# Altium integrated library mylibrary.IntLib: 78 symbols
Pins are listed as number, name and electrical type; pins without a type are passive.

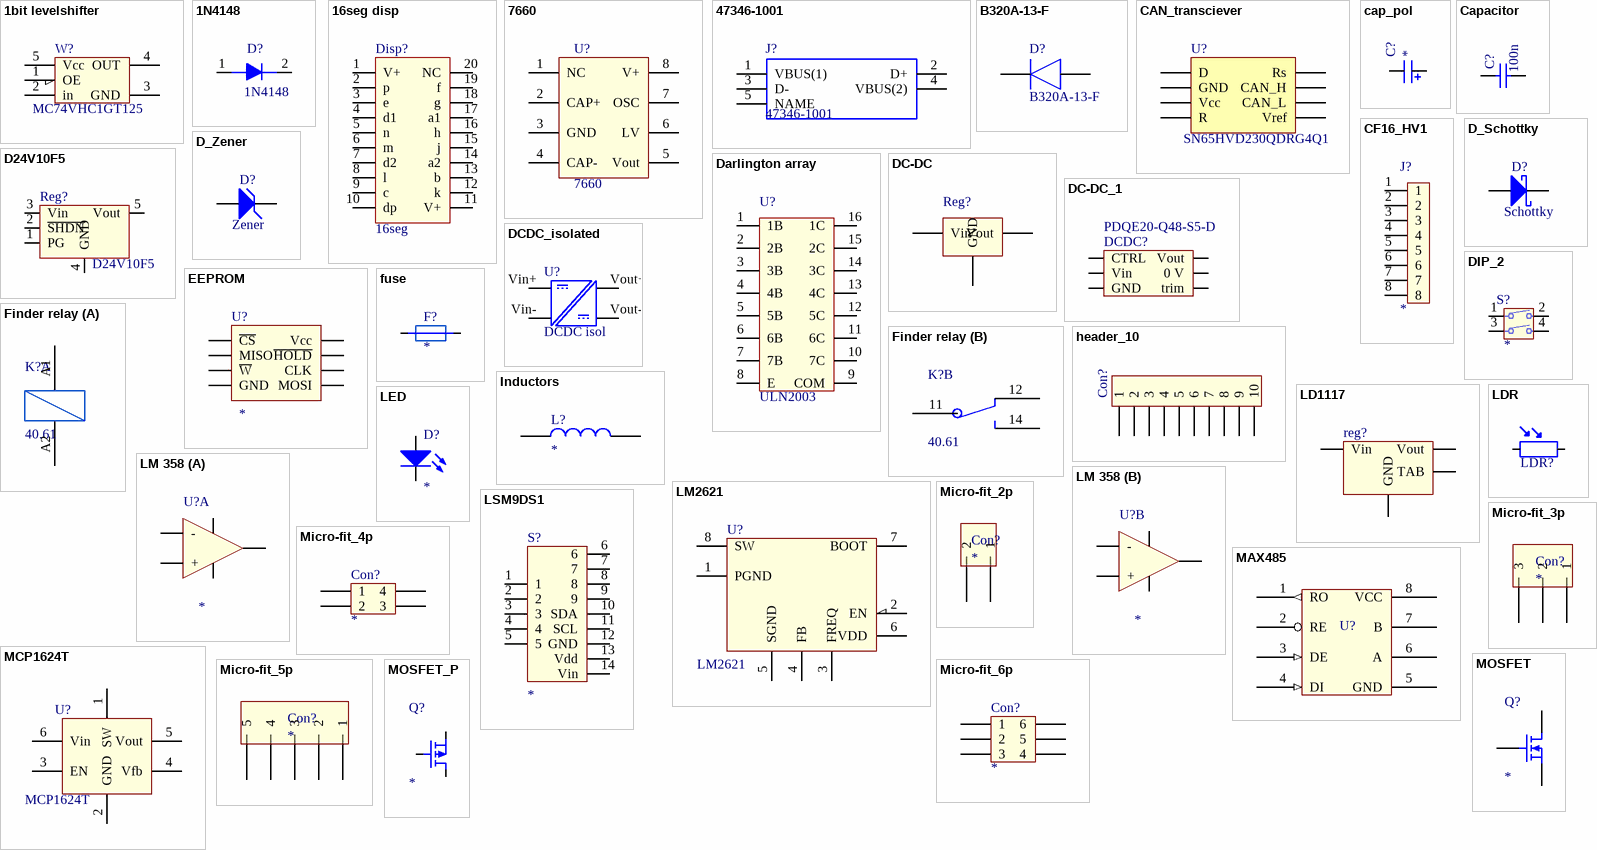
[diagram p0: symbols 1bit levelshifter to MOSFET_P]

## 1bit levelshifter
designator W?, comment MC74VHC1GT125
footprint SOT-353
pins: 1 OE, 2 in, 3 GND, 4 OUT, 5 Vcc

## 1N4148
designator D?
footprint 1N4148 (QuadroMELF (SOD-80))
pins: 1, 2

## 16seg disp
designator Disp?, comment 16seg
footprint PSA23-11SRWA (16 seg display)
pins: 1 V+, 2 p, 3 e, 4 d1, 5 n, 6 m, 7 d2, 8 l, 9 c, 10 dp, 11 V+, 12 k, 13 b, 14 a2, 15 j, 16 h, 17 a1, 18 g, 19 f, 20 NC

## 7660
designator U?
footprint SOIC127P600X170-8N (SOIC, 8-Leads, Body 4,90x3,90mm, Pitch 1,27mm, IPC Medium Density)
pins: 1 NC, 2 CAP+, 3 GND, 4 CAP-, 5 Vout, 6 LV, 7 OSC, 8 V+

## 47346-1001
designator J?
MOLEX - 47346-1001 - MULTIPOLE CONNECTOR
footprint 47346-0001
pins: 1 VBUS(1), 2 D+, 3 D-, 4 VBUS(2), 5 NAME

## B320A-13-F
designator D?
Diode Schottky 20V 3A 2Pin SMA Diodes Inc B320A-13-F, SMT Schottky Diode, 20V 3A, 2-Pin DO-214AC; Manufacturer_Name: Diodes Inc.; Allied_Number: 70437560; Geometry.Height: 2.2mm
footprint DIOM5226X220N
pins: 1 K, 2 A

## CAN_transciever
designator U?, comment SN65HVD230QDRG4Q1
SN65HVD230QDRG4Q1 SO-8
footprint SO-8 (SOIC, 8-Leads, Body 4,90x3,90mm, Pitch 1,27mm, IPC Medium Density)
pins: 1 D, 2 GND, 3 Vcc, 4 R, 5 Vref, 6 CAN_L, 7 CAN_H, 8 Rs

## cap_pol
designator C?
footprint CAP_5x5.5 (Aluminum Electrolytic Capacitor, Body 5,30x5,30x5,80mm, IPC Low Density)
footprint 1206_tantal (3216-18 AVX)
footprint elko_D5 (5mm diameter THT elko)
footprint 2917_pol (Vishay tantalum)
footprint UHE1A472MHD (12.5x35.5 ALU ELKO)
footprint 8x20 mm ELKO
footprint CAP_6.3x7.7 (6,3x7,7)
pins: 1, 2

## Capacitor
designator C?, comment 100n
footprint 0805_cap
footprint CAP0603
footprint cap 2.54 THT (ceramic THT capacitor)
footprint 1206_cap
pins: 1, 2

## CF16_HV1
designator J?
footprint CF16-HV1
pins: 1, 2, 3, 4, 5, 6, 7, 8

## D24V10F5
designator Reg?
footprint D24V10F5
pins: 1 PG, 2 ~{SHDN}, 3 Vin, 4 GND, 5 Vout

## D_Schottky
designator D?, comment Schottky
footprint DO-214AC (Molded Diode, 2-Leads, Body 4,31x2,49mm)
pins: 1, 2

## D_Zener
designator D?, comment Zener
footprint SOD-123 (SODFL, 2-Leads, Body 1,60x3,75mm)
pins: 1, 2

## Darlington array
designator U?, comment ULN2003
footprint SOP16
pins: 1 1B, 2 2B, 3 3B, 4 4B, 5 5B, 6 6B, 7 7B, 8 E, 9 COM, 10 7C, 11 6C, 12 5C, 13 4C, 14 3C, 15 2C, 16 1C

## DC-DC
designator Reg?  (value not drawn)
Adjustable voltage supply
footprint SIP3
footprint SIP3 - vert
footprint VXO7805-500
footprint VXO7805-1000
footprint VXO7805-500 - flat (flattened edition)
pins: 1 Vin, 2 GND, 3 Vout

## DC-DC_1
designator DCDC?, comment PDQE20-Q48-S5-D
footprint PDQE20-Q48-S5-D (CUI DC-DC 5V@4A)
pins: 1 CTRL, 2 GND, 3 Vin, 4 Vout, 5 trim, 6 0 V

## DCDC_isolated
designator U?, comment DCDC isol
footprint RI3
footprint SIP7-4 (4 pin SIP7 package)
pins: Vin+, Vin-, Vout+, Vout-

## DIP_2
designator S?
footprint 1-2319848-2
pins: 1, 2, 3, 4

## EEPROM
designator U?
M95512-DFMN6TP
footprint SO-8 (SOIC, 8-Leads, Body 4,90x3,90mm, Pitch 1,27mm, IPC Medium Density)
pins: 1 ~{CS}, 2 MISO, 3 ~{W}, 4 GND, 5 MOSI, 6 CLK, 7 ~{HOLD}, 8 Vcc

## Finder relay
designator K?, comment 40.61
footprint Finder 40.61 (40.61.7.012.2020 SPDT 16A)
part A pins: A1, A2
part B pins: 11, 12, 14

## fuse
designator F?
footprint Littelfuse_01530008 (Fuse holder w fuse)
footprint 3557-2 (Keystone fuse holder w fuse)
footprint 3557 (Keystone fuse holder w fuse)
footprint 1206_fuse (Bell fuse)
pins: 1, 2

## header_10
designator Con?, comment Header_10  (value not drawn)
footprint BM10B-SRSS-TB (1mm pitch JST-SH)
pins: 1, 2, 3, 4, 5, 6, 7, 8, 9, 10

## Inductors
designator L?
footprint 1812 (1812 size inductor)
footprint HC1-100-R (Precision Wire Wound Inductor, 2-Leads, Body 13,00x13,00mm, IPC Medium Density)
pins: 1, 2

## LD1117
designator reg?  (value not drawn)
footprint SOT230P700X180-4N (SOT223, 4-Leads, Body 6,50x7,00mm (avg), Pitch 2,30mm, IPC Medium Density)
footprint SOT223
pins: 1 GND, 2 Vout, 3 Vin, 4 TAB

## LDR
designator LDR?  (value not drawn)
footprint LDR (pitch 3.7mm)
pins: 1, 2

## LED
designator D?
footprint LED_5mm (std 5mm LED)
footprint EVL-BHC-AN1P2 (0805_Blue)
footprint EVL-GHC-XS1T2M (0805_Green)
footprint EVL-R6C-AQ1R2B (0805_Red)
footprint EVL-Y2C-CP2Q2B (0805_Yellow)
pins: 1, 2

## LM2621
designator U?
footprint VSSOP_8
pins: 1 PGND (power), 2 EN, 3 FREQ, 4 FB, 5 SGND (power), 6 VDD (power), 7 BOOT (power), 8 SW (power)

## LM 358
designator U?
footprint SO-8 (SOIC, 8-Leads, Body 4,90x3,90mm, Pitch 1,27mm, IPC Medium Density)
part A pins: 1 out, 2 -, 3 +, 4 GND, 8 Vcc
part B pins: 4 GND, 5 +, 6 -, 7 out, 8 Vcc

## LSM9DS1
designator S?
footprint DS1
pins: 1, 2, 3, 4, 5, 6, 7, 8, 9, 10 SDA, 11 SCL, 12 GND, 13 Vdd, 14 Vin

## MAX485
designator U?  (value not drawn)
footprint DIP8
footprint SOIC127P600X170-8N (SOIC, 8-Leads, Body 4,90x3,90mm, Pitch 1,27mm, IPC Medium Density)
pins: 1 RO (out), 2 RE, 3 DE (in), 4 DI (in), 5 GND (power), 6 A, 7 B, 8 VCC (power)

## MCP1624T
designator U?
footprint SOT23 (SOT23, 6-Leads, Body 2,90x3,10mm, Pitch 0,95mm, IPC Medium Density)
pins: 1 SW, 2 GND, 3 EN, 4 Vfb, 5 Vout, 6 Vin

## Micro-fit_2p
designator Con?
footprint Micro-fit_2P (horizontal)
pins: 1, 2

## Micro-fit_3p
designator Con?
footprint Micro-fit_3P (horizontal)
footprint Micro-fit_3P_v (vertical)
pins: 1, 2, 3

## Micro-fit_4p
designator Con?
footprint Micro-fit_4P (THT, double row, vertical)
pins: 1, 2, 3, 4

## Micro-fit_5p
designator Con?
footprint Micro-fit_5P (horizontal)
pins: 1, 2, 3, 4, 5

## Micro-fit_6p
designator Con?
footprint Micro-fit_6P (THT, double row, vertical)
pins: 1, 2, 3, 4, 5, 6

## MOSFET
designator Q?
footprint SOT323 (SOT23, 3-Leads, Body 1,90x2,10mm, Pitch 0,65mm, IPC Medium Density)
footprint SOT23-3 (DMN6140LQ-7)
footprint TO-220-3
pins: D, G, S

## MOSFET_P
designator Q?
footprint SOT323 (SOT23, 3-Leads, Body 1,90x2,10mm, Pitch 0,65mm, IPC Medium Density)
footprint SOT23-3 (DMN6140LQ-7)
footprint TO-220-3
pins: D, G, S

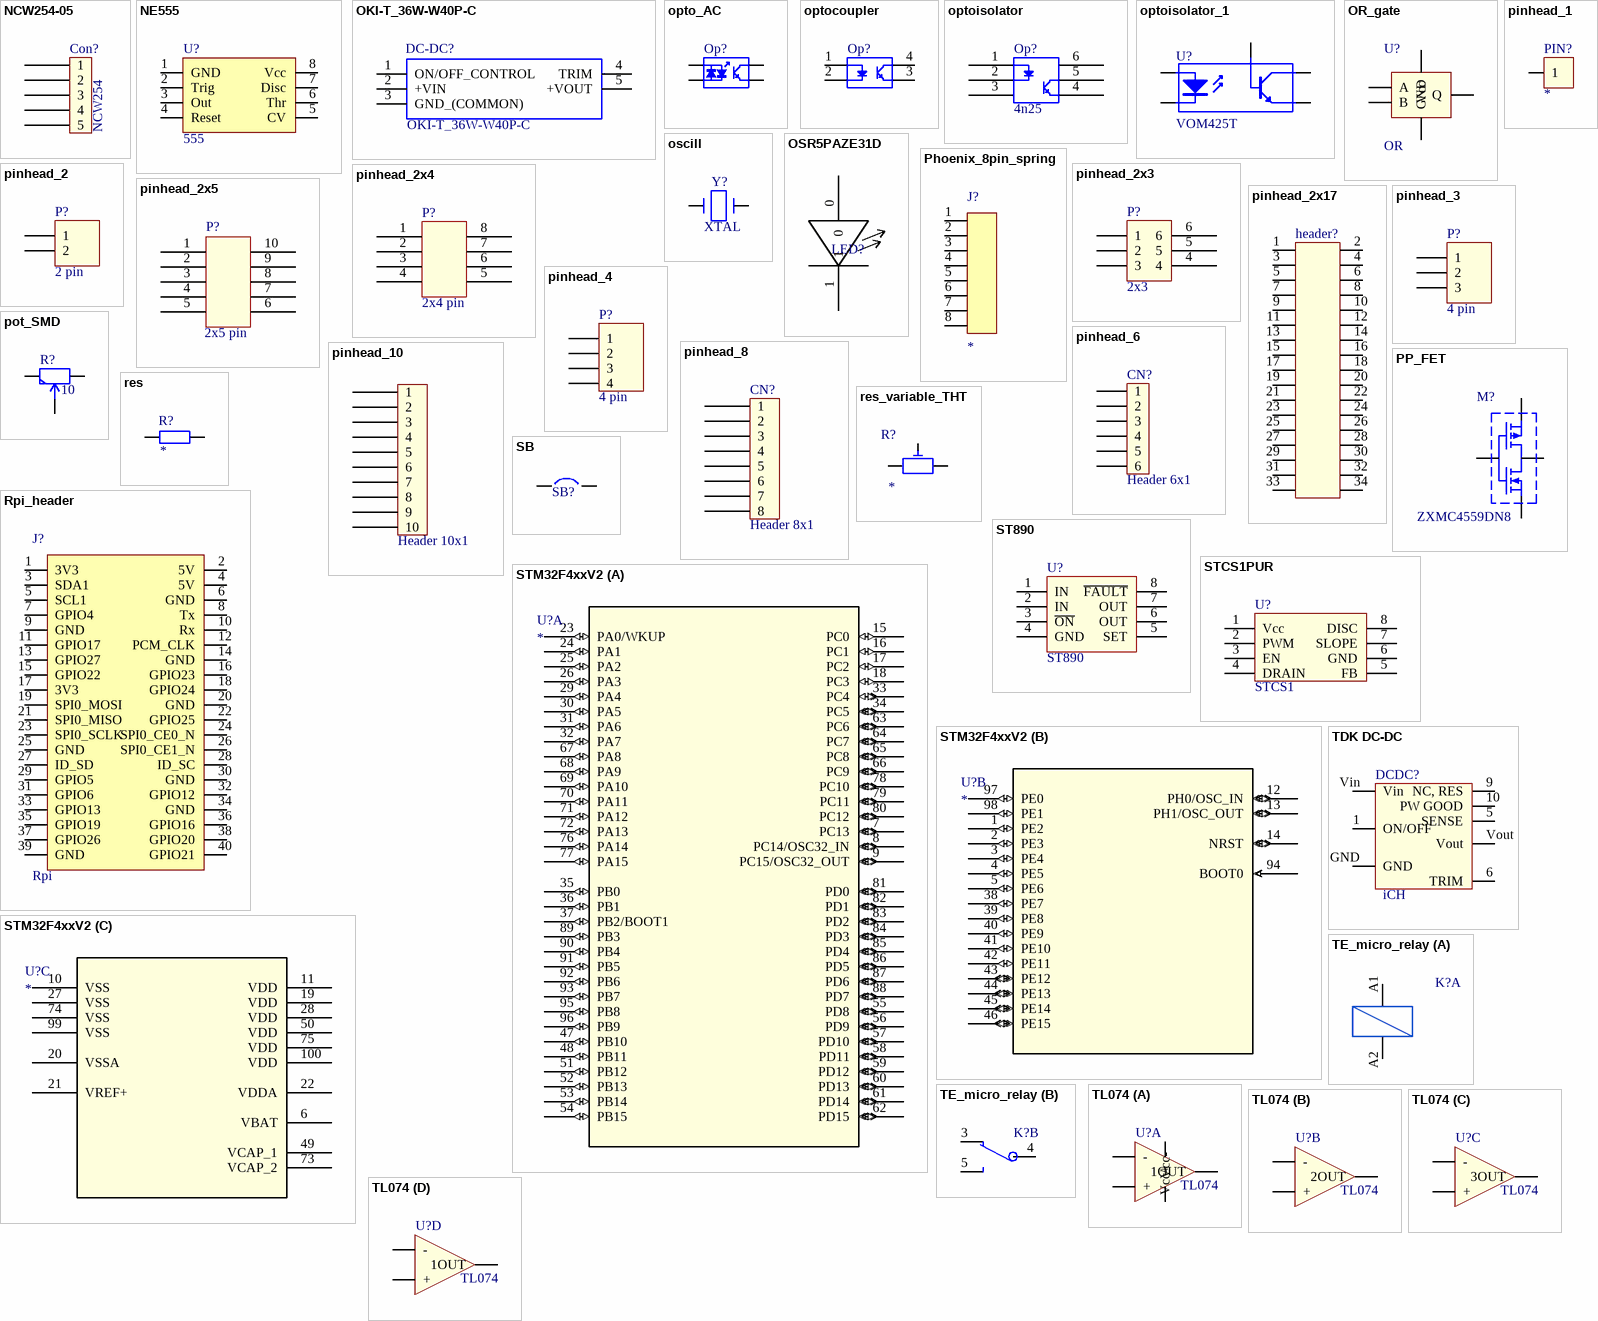
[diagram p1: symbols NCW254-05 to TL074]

## NCW254-05
designator Con?, comment NCW254
footprint NCW254_V5
pins: 1, 2, 3, 4, 5

## NE555
designator U?, comment 555
footprint SO-8 (SOIC, 8-Leads, Body 4,90x3,90mm, Pitch 1,27mm, IPC Medium Density)
pins: 1 GND, 2 Trig, 3 Out, 4 Reset, 5 CV, 6 Thr, 7 Disc, 8 Vcc

## OKI-T_36W-W40P-C
designator DC-DC?
Non-Isolated DC/DC Converters 36W 5.021-15.5Vout 3A 24Vin PosPolarity; Manufacturer_Name: Murata Electronics; Manufacturer_Part_Number: OKI-T/36W-W40N-C; Geometry.Height: 8mm
footprint OKIT36WW40NC
pins: 1 ON/OFF_CONTROL, 2 +VIN, 3 GND_(COMMON), 4 TRIM, 5 +VOUT

## opto_AC
designator Op?
SFH628A-3X017T
footprint SMD-4
pins: 1, 2, 3, 4

## optocoupler
designator Op?
footprint PDIP-4 Gull Wing
pins: 1, 2, 3, 4

## optoisolator
designator Op?, comment 4n25
footprint 4N25S (SMD)
pins: 1, 2, 3, 4, 5, 6

## optoisolator_1
designator U?, comment VOM425T
footprint SOP5 (Small Outline; 6 Leads (1 Absent); Body Width 4.4 mm; Pitch 1.27 mm)
pins: 1 A "Anode", 3 K "Cathode", 4 E "Emitter", 5 C "Collector", 6 B "Base"

## OR_gate
designator U?, comment OR
74HC1G32GW.125
footprint SOT-353
pins: 1 B, 2 A, 3 GND, 4 Q, 5 Vcc

## oscill
designator Y?, comment XTAL
footprint HC49SM
footprint crystal_2.5x3.2
pins: 1, 2

## OSR5PAZE31D
designator LED?  (value not drawn)
footprint superflux_case
pins: 0, 1

## Phoenix_8pin_spring
designator J?
footprint Phoenix_8pin
footprint DG235-3.81-08P
pins: 1, 2, 3, 4, 5, 6, 7, 8

## pinhead_1
designator PIN?
footprint PIN_1_single
footprint M4_terminal (PCB-66)
pins: 1

## pinhead_2
designator P?, comment 2 pin
footprint pin_2_254
footprint hole_2_254
pins: 1, 2

## pinhead_2x3
designator P?, comment 2x3
footprint pin_2x3_254
pins: 1, 2, 3, 4, 5, 6

## pinhead_2x4
designator P?, comment 2x4 pin
footprint pin_2x4_254
pins: 1, 2, 3, 4, 5, 6, 7, 8

## pinhead_2x5
designator P?, comment 2x5 pin
footprint pin_2x5_254
pins: 1, 2, 3, 4, 5, 6, 7, 8, 9, 10

## pinhead_2x17
designator header?  (value not drawn)
footprint socket_2x17_254
pins: 1, 2, 3, 4, 5, 6, 7, 8, 9, 10, 11, 12, 13, 14, 15, 16, 17, 18, 19, 20, 21, 22, 23, 24, 25, 26, 27, 28, 29, 30, 31, 32, 33, 34

## pinhead_3
designator P?, comment 4 pin
footprint pin_3_254
footprint hole_3_254
pins: 1, 2, 3

## pinhead_4
designator P?, comment 4 pin
footprint pin_4_254
footprint pin_4_254_down
footprint socket_4_254
pins: 1, 2, 3, 4

## pinhead_6
designator CN?, comment Header 6x1
footprint pin_6_254
pins: 1, 2, 3, 4, 5, 6

## pinhead_8
designator CN?, comment Header 8x1
footprint PIN_8_254
pins: 1, 2, 3, 4, 5, 6, 7, 8

## pinhead_10
designator CN?, comment Header 10x1
footprint PIN_10_254
pins: 1, 2, 3, 4, 5, 6, 7, 8, 9, 10

## pot_SMD
designator R?, comment 10
PVG, SMT top adj cermet trimmer,10Ohm Bourns PVG5A Series 12-Turn SMD Cermet Trimmer Resistor with J-Hook Terminations, 10R 10% 1/4W 150ppm/C Top Adjust; Manufacturer_Part_Number: PVG5A502C03R00; Geometry.Height: 5mm
footprint PVG5A100C03R00
footprint trim_10.3 (10.3x4.5mm body vertical)
pins: 1, 2, 3

## PP_FET
designator M?, comment ZXMC4559DN8
footprint SO-8 - P-P (SO-8 push-pull FET)
pins: D, G, S1, S2

## res
designator R?
footprint RES1206 (Chip Resistor, 2-Leads, Body 3,15x1,60mm, IPC Medium Density)
footprint RES0805
footprint RES1210
footprint RES1218
footprint RES2512
footprint RES0603
pins: 0, 1

## res_variable_THT
designator R?
footprint T67Y (SR Passives potentiometer)
footprint 3296W (Bourns 3296W)
pins: 1, 2, 3

## Rpi_header
designator J?, comment Rpi
footprint Rpi_header
pins: 1 3V3, 2 5V, 3 SDA1, 4 5V, 5 SCL1, 6 GND, 7 GPIO4, 8 Tx, 9 GND, 10 Rx, 11 GPIO17, 12 PCM_CLK, 13 GPIO27, 14 GND, 15 GPIO22, 16 GPIO23, 17 3V3, 18 GPIO24, 19 SPI0_MOSI, 20 GND, 21 SPI0_MISO, 22 GPIO25, 23 SPI0_SCLK, 24 SPI0_CE0_N, 25 GND, 26 SPI0_CE1_N, 27 ID_SD, 28 ID_SC, 29 GPIO5, 30 GND, 31 GPIO6, 32 GPIO12, 33 GPIO13, 34 GND, 35 GPIO19, 36 GPIO16, 37 GPIO26, 38 GPIO20, 39 GND, 40 GPIO21

## SB
designator SB?  (value not drawn)
footprint Circuit Braker
pins: 1, 2

## ST890
designator U?
Current limited high-side switch
footprint SO-8 (SOIC, 8-Leads, Body 4,90x3,90mm, Pitch 1,27mm, IPC Medium Density)
pins: 1 IN, 2 IN, 3 ~{ON}, 4 GND, 5 SET, 6 OUT, 7 OUT, 8 ~{FAULT}

## STCS1PUR
designator U?, comment STCS1
Constant current LED driver max 1.5Amps
footprint DFN8 (DFN, 8-Leads, Body 3,00x3,00mm, Pitch 0,50mm)
pins: 1 Vcc, 2 PWM, 3 EN, 4 DRAIN, 5 FB, 6 GND, 7 SLOPE, 8 DISC

## STM32F4xxV2
designator U?
Imported; Manufacturer_Part_Number: stm32f4xxv2; Vendor: STMicroelectronics; C: Copyright (C) 2016 Accelerated Designs. All rights reserved
footprint LQFP100 14x14 (LQFP, 100-Leads, Body 14,00x14,00mm, Pitch 0,50mm, IPC Medium Density)
part A pins: 7 PC13 (io), 8 PC14/OSC32_IN (io), 9 PC15/OSC32_OUT (io), 15 PC0 (io), 16 PC1 (io), 17 PC2 (io), 18 PC3 (io), 23 PA0/WKUP (io), 24 PA1 (io), 25 PA2 (io), 26 PA3 (io), 29 PA4 (io), 30 PA5 (io), 31 PA6 (io), 32 PA7 (io), 33 PC4 (io), 34 PC5 (io), 35 PB0 (io), 36 PB1 (io), 37 PB2/BOOT1 (io), 47 PB10 (io), 48 PB11 (io), 51 PB12 (io), 52 PB13 (io), 53 PB14 (io), 54 PB15 (io), 55 PD8 (io), 56 PD9 (io), 57 PD10 (io), 58 PD11 (io), 59 PD12 (io), 60 PD13 (io), 61 PD14 (io), 62 PD15 (io), 63 PC6 (io), 64 PC7 (io), 65 PC8 (io), 66 PC9 (io), 67 PA8 (io), 68 PA9 (io), 69 PA10 (io), 70 PA11 (io), 71 PA12 (io), 72 PA13 (io), 76 PA14 (io), 77 PA15 (io), 78 PC10 (io), 79 PC11 (io), 80 PC12 (io), 81 PD0 (io), 82 PD1 (io), 83 PD2 (io), 84 PD3 (io), 85 PD4 (io), 86 PD5 (io), 87 PD6 (io), 88 PD7 (io), 89 PB3 (io), 90 PB4 (io), 91 PB5 (io), 92 PB6 (io), 93 PB7 (io), 95 PB8 (io), 96 PB9 (io)
part B pins: 1 PE2 (io), 2 PE3 (io), 3 PE4 (io), 4 PE5 (io), 5 PE6 (io), 12 PH0/OSC_IN (io), 13 PH1/OSC_OUT (io), 14 NRST (io), 38 PE7 (io), 39 PE8 (io), 40 PE9 (io), 41 PE10 (io), 42 PE11 (io), 43 PE12 (io), 44 PE13 (io), 45 PE14 (io), 46 PE15 (io), 94 BOOT0 (in), 97 PE0 (io), 98 PE1 (io)
part C pins: 6 VBAT (power), 10 VSS (power), 11 VDD (power), 19 VDD (power), 20 VSSA (power), 21 VREF+ (power), 22 VDDA (power), 27 VSS (power), 28 VDD (power), 49 VCAP_1 (power), 50 VDD (power), 73 VCAP_2 (power), 74 VSS (power), 75 VDD (power), 99 VSS (power), 100 VDD (power)

## TDK DC-DC
designator DCDC?, comment iCH
iCH12012A007V-007-R
footprint iCH12012A (iCH12012A007V-007-R)
pins: 1 ON/OFF, 5 SENSE, 6 TRIM, 9 NC, RES, 10 PW GOOD, GND, Vin, Vout

## TE_micro_relay
designator K?  (value not drawn)
V23086C1001A403
footprint V23086C1001A403
part A pins: A1, A2
part B pins: 3, 4, 5

## TL074
designator U?
footprint SOIC-14 (SOIC-14, Pitch 1.27mm)
part A pins: 1 1OUT, 2 -, 3 +, 4 Vcc+, 11 Vcc-
part B pins: 5 +, 6 -, 7 2OUT
part C pins: 8 3OUT, 9 -, 10 +
part D pins: 12 +, 13 -, 14 1OUT

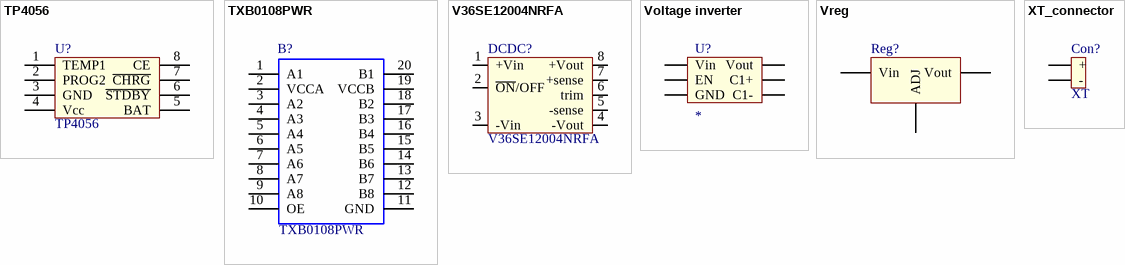
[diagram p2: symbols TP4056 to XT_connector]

## TP4056
designator U?
footprint SOP-8 (SOP, 8-Leads, Body 5,00x3,80mm, Pitch 1,27mm, Thermal Pad 3,00x3,00mm)
pins: 1 TEMP1, 2 PROG2, 3 GND, 4 Vcc, 5 BAT, 6 ~{STDBY}, 7 ~{CHRG}, 8 CE

## TXB0108PWR
designator B?
8-Bit Bidirectional Voltage-Level Shifter with Auto Direction Sensing and +/-15-kV ESD Protect; Manufacturer_Name: Texas Instruments; Geometry.Height: 1.2mm
footprint TSSOP-20
pins: 1 A1, 2 VCCA (power), 3 A2, 4 A3, 5 A4, 6 A5, 7 A6, 8 A7, 9 A8, 10 OE, 11 GND, 12 B8, 13 B7, 14 B6, 15 B5, 16 B4, 17 B3, 18 B2, 19 VCCB (power), 20 B1

## V36SE12004NRFA
designator DCDC?
footprint 1/16 Brick (V36SE12004NRFA)
pins: 1 +Vin, 2 ~{ON}/OFF, 3 -Vin, 4 -Vout, 5 -sense, 6 trim, 7 +sense, 8 +Vout

## Voltage inverter
designator U?
footprint SOT23-6 (SOT23, 6-Leads, Pitch 0,95mm)
pins: 1 Vout, 2 GND, 3 Vin, 4 EN, 5 C1+, 6 C1-

## Vreg
designator Reg?  (value not drawn)
Adjustable voltage supply
footprint TO-220
pins: 1 ADJ, 2 Vout, 3 Vin

## XT_connector
designator Con?, comment XT
footprint XT30PW_F
footprint XT30PW_M
footprint XT60PW_F
footprint XT60PW_M
footprint XT90PW_F
footprint XT90PW_M
pins: 1 +, 2 -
